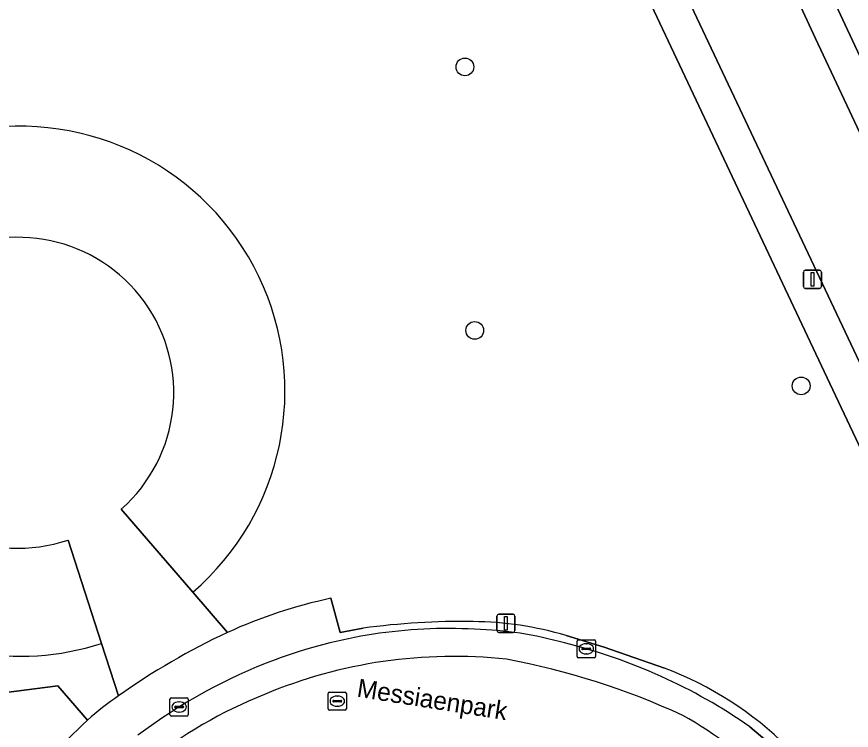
# Model space of a CAD drawing. Extents: x 159039 to 160102, y 381214 to 382524.
# Drawn here: x 159122.23 to 159168.11, y 381342.01 to 381381.25 of the extents above; entities that cross this region are included whole.
import ezdxf

# ---------------------------------------------------------------- set-up
doc = ezdxf.new("R2010")
doc.units = 0
for name, color, linetype in [('IMGEO_Boom', 7, 'Continuous'), ('IMGEO_Groenvoorziening', 7, 'Continuous'), ('IMGEO_Kolk', 7, 'Continuous'), ('IMGEO_Lichtmast', 7, 'Continuous'), ('IMGEO_Openbare_ruimte_label', 7, 'Continuous'), ('IMGEO_Parkeervlak_open', 7, 'Continuous'), ('IMGEO_Rijbaan_lokaal_gesloten', 7, 'Continuous'), ('IMGEO_Rijbaan_lokaal_open', 7, 'Continuous'), ('IMGEO_Rioolput', 7, 'Continuous'), ('IMGEO_Voetpad_open', 7, 'Continuous')]:
    doc.layers.add(name, color=color, linetype=linetype)

msp = doc.modelspace()

# ---------------------------------------------------------------- linework, layer by layer
at = {"layer": 'IMGEO_Boom'}
for centre in [(159146.869, 381378.489), (159147.408, 381364.001), (159165.352, 381360.947)]:
    msp.add_circle(centre, 0.489, dxfattribs=at)
at = {"layer": 'IMGEO_Groenvoorziening'}
for points in [[(159183.485, 381320.552), (159182.155, 381325.087), (159181.079, 381328.582), (159179.725, 381332.403), (159177.417, 381338.702), (159176.573, 381340.671), (159166.925, 381361.075), (159146.089, 381405.269)], [(159126.121, 381342.56), (159124.484, 381344.462), (159115.355, 381343.287), (159112.466, 381346.176), (159110.202, 381344.576), (159103.414, 381339.779), (159103.317, 381339.983), (159101.977, 381342.795), (159099.705, 381342.179), (159095.019, 381340.909), (159094.936, 381341.084), (159093.002, 381345.168), (159092.092, 381344.758), (159087.24, 381355.053), (159088.149, 381355.498), (159086.232, 381359.566), (159086.143, 381359.756), (159090.134, 381362.607), (159092.046, 381363.967), (159090.617, 381366.979), (159098.61, 381369.192), (159103.147, 381359.559), (159107.869, 381361.797)], [(159131.905, 381349.605), (159133.813, 381347.388)], [(159139.492, 381349.268), (159140.006, 381347.391), (159141.271, 381347.623)], [(159152.429, 381347.223), (159154.519, 381346.574), (159157.844, 381345.436)]]:
    msp.add_lwpolyline(points, dxfattribs=at)
for centre, radius, start, end in [((159122.399, 381360.654), 14.575, 310.7049, 175.5033), ((159145.07, 381322.901), 26.95, 101.9448, 114.6889), ((159146.687, 381308.382), 39.613, 89.0967, 97.8575), ((159147.165, 381329.556), 18.434, 73.4078, 89.546), ((159150.733, 381326.929), 19.826, 45.5782, 68.9821), ((159144.939, 381322.016), 27.86, 132.4902, 144.6178)]:
    msp.add_arc(centre, radius, start, end, dxfattribs=at)
at = {"layer": 'IMGEO_Kolk'}
for p, q in [((159153.041, 381346.066), (159153.041, 381346.918)), ((159153.116, 381346.992), (159153.968, 381346.992)), ((159153.529, 381346.772), (159153.554, 381346.772)), ((159154.042, 381346.918), (159154.042, 381346.066)), ((159153.3, 381346.486), (159153.3, 381346.498)), ((159153.738, 381346.449), (159153.34, 381346.449)), ((159153.343, 381346.535), (159153.741, 381346.535)), ((159153.784, 381346.498), (159153.784, 381346.486)), ((159153.968, 381345.992), (159153.116, 381345.992)), ((159153.552, 381346.212), (159153.527, 381346.212)), ((159130.652, 381342.869), (159130.652, 381343.721)), ((159130.727, 381343.795), (159131.579, 381343.795)), ((159131.14, 381343.575), (159131.165, 381343.575)), ((159131.653, 381343.721), (159131.653, 381342.869)), ((159130.911, 381343.289), (159130.911, 381343.301)), ((159131.349, 381343.252), (159130.951, 381343.252)), ((159130.954, 381343.338), (159131.352, 381343.338)), ((159131.395, 381343.301), (159131.395, 381343.289)), ((159131.579, 381342.795), (159130.727, 381342.795)), ((159131.163, 381343.015), (159131.138, 381343.015))]:
    msp.add_line(p, q, dxfattribs=at)
for points in [[(159153.041, 381346.066), (159153.041, 381346.918)], [(159153.116, 381346.992), (159153.968, 381346.992)], [(159154.042, 381346.918), (159154.042, 381346.066)], [(159153.968, 381345.992), (159153.116, 381345.992)], [(159130.652, 381342.869), (159130.652, 381343.721)], [(159130.727, 381343.795), (159131.579, 381343.795)], [(159131.653, 381343.721), (159131.653, 381342.869)], [(159131.579, 381342.795), (159130.727, 381342.795)]]:
    msp.add_lwpolyline(points, dxfattribs=at)
for centre, radius, start, end in [((159153.118, 381346.916), 0.0765, 91.552, 178.448), ((159153.118, 381346.916), 0.0765, 91.552, 178.448), ((159153.966, 381346.916), 0.0765, 1.552, 88.448), ((159153.966, 381346.916), 0.0765, 1.552, 88.448), ((159153.34, 381346.495), 0.0403, 85.8775, 175.7526), ((159153.337, 381346.485), 0.0366, 178.938, 274.7102), ((159153.741, 381346.492), 0.043, 264.8664, 352.4533), ((159153.745, 381346.497), 0.0386, 1.7309, 96.639), ((159153.118, 381346.068), 0.0765, 181.552, 268.448), ((159153.118, 381346.068), 0.0765, 181.552, 268.448), ((159153.966, 381346.068), 0.0765, 271.552, 358.448), ((159153.966, 381346.068), 0.0765, 271.552, 358.448), ((159130.729, 381343.719), 0.0765, 91.552, 178.448), ((159130.729, 381343.719), 0.0765, 91.552, 178.448), ((159131.577, 381343.719), 0.0765, 1.552, 88.448), ((159131.577, 381343.719), 0.0765, 1.552, 88.448), ((159130.951, 381343.298), 0.0403, 85.8775, 175.7526), ((159130.948, 381343.288), 0.0366, 178.938, 274.7102), ((159131.352, 381343.295), 0.043, 264.8664, 352.4533), ((159131.356, 381343.3), 0.0386, 1.7309, 96.639), ((159130.729, 381342.871), 0.0765, 181.552, 268.448), ((159130.729, 381342.871), 0.0765, 181.552, 268.448), ((159131.577, 381342.871), 0.0765, 271.552, 358.448), ((159131.577, 381342.871), 0.0765, 271.552, 358.448)]:
    msp.add_arc(centre, radius, start, end, dxfattribs=at)
for centre, major_axis, ratio, start_param, end_param in [((159153.528, 381346.492), (-0.387, 0.002), 0.722429, 4.712389, 7.853982), ((159153.553, 381346.492), (-0.39, 0.002), 0.717154, 1.570796, 4.712389), ((159131.139, 381343.295), (-0.387, 0.002), 0.722429, 4.712389, 7.853982), ((159131.164, 381343.295), (-0.39, 0.002), 0.717154, 1.570796, 4.712389)]:
    msp.add_ellipse(centre, major_axis=major_axis, ratio=ratio, start_param=start_param, end_param=end_param, dxfattribs=at)
at = {"layer": 'IMGEO_Lichtmast'}
for p, q in [((159165.476, 381366.408), (159165.476, 381367.208)), ((159165.476, 381367.208), (159165.476, 381366.408)), ((159165.576, 381367.308), (159166.366, 381367.308)), ((159166.366, 381367.308), (159165.576, 381367.308)), ((159166.466, 381367.208), (159166.466, 381366.408)), ((159166.466, 381366.408), (159166.466, 381367.208)), ((159166.366, 381366.308), (159165.576, 381366.308)), ((159165.576, 381366.308), (159166.366, 381366.308)), ((159148.624, 381347.49), (159148.624, 381348.29)), ((159148.624, 381348.29), (159148.624, 381347.49)), ((159148.724, 381348.39), (159149.514, 381348.39)), ((159149.514, 381348.39), (159148.724, 381348.39)), ((159149.614, 381348.29), (159149.614, 381347.49)), ((159149.614, 381347.49), (159149.614, 381348.29)), ((159149.514, 381347.39), (159148.724, 381347.39)), ((159148.724, 381347.39), (159149.514, 381347.39))]:
    msp.add_line(p, q, dxfattribs=at)
for points in [[(159165.896, 381367.183), (159166.046, 381367.183), (159166.046, 381366.433), (159165.896, 381366.433), (159165.896, 381367.183)], [(159149.044, 381348.265), (159149.194, 381348.265), (159149.194, 381347.515), (159149.044, 381347.515), (159149.044, 381348.265)]]:
    msp.add_lwpolyline(points, dxfattribs=at)
for centre, start, end in [((159165.576, 381367.208), 90, 180), ((159165.576, 381367.208), 90, 180), ((159166.366, 381367.208), 0, 90), ((159166.366, 381367.208), 360, 90), ((159165.576, 381366.408), 180, 270), ((159165.576, 381366.408), 180, 270), ((159166.366, 381366.408), 270, 0), ((159166.366, 381366.408), 270, 0), ((159148.724, 381348.29), 90, 180), ((159148.724, 381348.29), 90, 180), ((159149.514, 381348.29), 0, 90), ((159149.514, 381348.29), 360, 90), ((159148.724, 381347.49), 180, 270), ((159148.724, 381347.49), 180, 270), ((159149.514, 381347.49), 270, 0), ((159149.514, 381347.49), 270, 0)]:
    msp.add_arc(centre, 0.1, start, end, dxfattribs=at)
at = {"layer": 'IMGEO_Parkeervlak_open'}
for points in [[(159149.4, 381415.463), (159151.164, 381411.865), (159152.42, 381409.329), (159163.115, 381386.6), (159166.148, 381380.052), (159173.158, 381365.109), (159175.314, 381360.345), (159181.799, 381346.618), (159183.007, 381344.058), (159183.216, 381343.614), (159183.92, 381342.134)], [(159184.313, 381345.459), (159183.083, 381348.082), (159176.928, 381361.094), (159174.777, 381365.849), (159167.763, 381380.799), (159164.73, 381387.348), (159154.272, 381409.573), (159152.189, 381413.877)], [(159127.976, 381354.171), (159131.905, 381349.605)], [(159126.888, 381346.787), (159125.047, 381352.474)]]:
    msp.add_lwpolyline(points, dxfattribs=at)
for centre, radius, start, end in [((159122.399, 381360.654), 14.575, 310.7049, 175.5033), ((159122.311, 381360.572), 8.547, 311.5082, 288.666), ((159122.4, 381360.655), 14.576, 175.5055, 287.9327)]:
    msp.add_arc(centre, radius, start, end, dxfattribs=at)
at = {"layer": 'IMGEO_Rijbaan_lokaal_gesloten'}
msp.add_lwpolyline([(159167.117, 381337.852), (159166.169, 381338.89), (159165.101, 381340.032), (159162.533, 381342.21)], dxfattribs=at)
for centre, radius, start, end in [((159145.973, 381320.307), 27.302, 86.9999, 110.4367), ((159146.818, 381327.34), 20.24, 74.1615, 88.3462), ((159144.963, 381316.887), 30.821, 55.246, 76.1485), ((159146.94, 381317.82), 29.97, 110.508, 127.0554), ((159146.237, 381319.215), 26.859, 83.7681, 112.7561), ((159141.652, 381305.595), 41.012, 65.2183, 79.4619), ((159145.01, 381320.915), 24.821, 111.6617, 146.5678), ((159145.929, 381320.087), 26.153, 33.0618, 60.4116)]:
    msp.add_arc(centre, radius, start, end, dxfattribs=at)
at = {"layer": 'IMGEO_Rijbaan_lokaal_open'}
msp.add_lwpolyline([(159183.007, 381344.058), (159181.799, 381346.618), (159175.314, 381360.345), (159173.158, 381365.109), (159166.148, 381380.052), (159163.115, 381386.6), (159152.42, 381409.329), (159147.453, 381406.965), (159147.869, 381406.077), (159168.866, 381361.603), (159178.201, 381341.808)], close=True, dxfattribs=at)
for points in [[(159133.813, 381347.388), (159131.905, 381349.605), (159127.976, 381354.171)], [(159125.047, 381352.474), (159126.888, 381346.787), (159127.822, 381343.901)]]:
    msp.add_lwpolyline(points, dxfattribs=at)
for centre, radius, start, end in [((159122.311, 381360.572), 8.547, 311.5082, 288.666), ((159149.379, 381313.755), 37.06, 114.8349, 125.5673), ((159146.237, 381319.215), 26.859, 83.7681, 112.7561), ((159141.652, 381305.595), 41.012, 65.2183, 79.4619), ((159145.01, 381320.915), 24.821, 111.6617, 146.5678), ((159145.929, 381320.087), 26.153, 33.0618, 60.4116)]:
    msp.add_arc(centre, radius, start, end, dxfattribs=at)
at = {"layer": 'IMGEO_Rioolput'}
for p, q in [((159139.35, 381343.186), (159139.35, 381344.038)), ((159139.425, 381344.112), (159140.277, 381344.112)), ((159140.351, 381344.038), (159140.351, 381343.186)), ((159139.609, 381343.606), (159139.609, 381343.618)), ((159140.047, 381343.569), (159139.649, 381343.569)), ((159139.652, 381343.655), (159140.05, 381343.655)), ((159139.838, 381343.892), (159139.863, 381343.892)), ((159140.093, 381343.618), (159140.093, 381343.606)), ((159140.277, 381343.112), (159139.425, 381343.112)), ((159139.861, 381343.332), (159139.836, 381343.332))]:
    msp.add_line(p, q, dxfattribs=at)
for points in [[(159139.35, 381343.186), (159139.35, 381344.038)], [(159139.425, 381344.112), (159140.277, 381344.112)], [(159140.351, 381344.038), (159140.351, 381343.186)], [(159140.277, 381343.112), (159139.425, 381343.112)]]:
    msp.add_lwpolyline(points, dxfattribs=at)
for centre, radius, start, end in [((159139.427, 381344.036), 0.0765, 91.552, 178.448), ((159139.427, 381344.036), 0.0765, 91.552, 178.448), ((159140.275, 381344.036), 0.0765, 1.552, 88.448), ((159140.275, 381344.036), 0.0765, 1.552, 88.448), ((159139.649, 381343.615), 0.0403, 85.8775, 175.7526), ((159139.646, 381343.605), 0.0366, 178.938, 274.7102), ((159140.05, 381343.612), 0.043, 264.8664, 352.4533), ((159140.054, 381343.617), 0.0386, 1.7309, 96.639), ((159139.427, 381343.188), 0.0765, 181.552, 268.448), ((159139.427, 381343.188), 0.0765, 181.552, 268.448), ((159140.275, 381343.188), 0.0765, 271.552, 358.448), ((159140.275, 381343.188), 0.0765, 271.552, 358.448)]:
    msp.add_arc(centre, radius, start, end, dxfattribs=at)
for centre, major_axis, ratio, start_param, end_param in [((159139.837, 381343.612), (-0.387, 0.002), 0.722429, 4.712389, 7.853982), ((159139.862, 381343.612), (-0.39, 0.002), 0.717154, 1.570796, 4.712389)]:
    msp.add_ellipse(centre, major_axis=major_axis, ratio=ratio, start_param=start_param, end_param=end_param, dxfattribs=at)
at = {"layer": 'IMGEO_Voetpad_open'}
for points in [[(159138.838, 381420.676), (159140.29, 381417.535), (159146.089, 381405.269), (159166.925, 381361.075), (159176.573, 381340.671), (159177.417, 381338.702), (159179.725, 381332.403), (159181.079, 381328.582), (159182.155, 381325.087), (159183.485, 381320.552), (159183.58, 381320.071), (159185.351, 381312.004), (159185.783, 381309.99), (159186.535, 381306.759), (159187.645, 381285.734), (159188.179, 381280.338)], [(159183.211, 381330.948), (159181.577, 381334.596), (159179.38, 381339.291), (159178.484, 381341.207), (159178.201, 381341.808), (159168.866, 381361.603), (159147.869, 381406.077), (159147.453, 381406.965), (159146.252, 381409.527), (159143.611, 381415.16), (159140.88, 381420.897)], [(159152.189, 381413.877), (159154.272, 381409.573), (159164.73, 381387.348), (159167.763, 381380.799), (159174.777, 381365.849), (159176.928, 381361.094), (159183.083, 381348.082), (159184.313, 381345.459)], [(159107.869, 381361.797), (159103.147, 381359.559), (159102.742, 381359.367), (159103.333, 381358.127), (159104.731, 381358.787), (159106.076, 381355.9), (159104.764, 381355.281), (159103.367, 381354.621), (159104.33, 381353.525), (159107.859, 381349.512), (159110.202, 381344.576), (159112.466, 381346.176), (159115.355, 381343.287), (159124.484, 381344.462), (159126.121, 381342.56)], [(159141.271, 381347.623), (159140.006, 381347.391), (159139.492, 381349.268)], [(159157.844, 381345.436), (159154.519, 381346.574), (159152.429, 381347.223)], [(159127.822, 381343.901), (159126.888, 381346.787)], [(159162.533, 381342.21), (159165.101, 381340.032), (159166.169, 381338.89), (159167.117, 381337.852)]]:
    msp.add_lwpolyline(points, dxfattribs=at)
for centre, radius, start, end in [((159122.4, 381360.655), 14.576, 175.5055, 287.9327), ((159145.07, 381322.901), 26.95, 101.9448, 114.6889), ((159146.687, 381308.382), 39.613, 89.0967, 97.8575), ((159147.165, 381329.556), 18.434, 73.4078, 89.546), ((159149.379, 381313.755), 37.06, 114.8349, 125.5673), ((159145.973, 381320.307), 27.302, 86.9999, 110.4367), ((159146.818, 381327.34), 20.24, 74.1615, 88.3462), ((159144.963, 381316.887), 30.821, 55.246, 76.1485), ((159146.94, 381317.82), 29.97, 110.508, 127.0554), ((159150.733, 381326.929), 19.826, 45.5782, 68.9821), ((159135.188, 381332.809), 13.315, 123.5853, 132.9163), ((159135.188, 381332.809), 13.315, 123.5853, 132.9163), ((159144.939, 381322.016), 27.86, 132.4902, 144.6178)]:
    msp.add_arc(centre, radius, start, end, dxfattribs=at)

# ---------------------------------------------------------------- texts
at = {"layer": 'IMGEO_Openbare_ruimte_label'}
msp.add_text('Messiaenpark', height=1, rotation=351.0274, dxfattribs=at).set_placement((159140.887, 381343.865))

doc.saveas('drawing.dxf')
